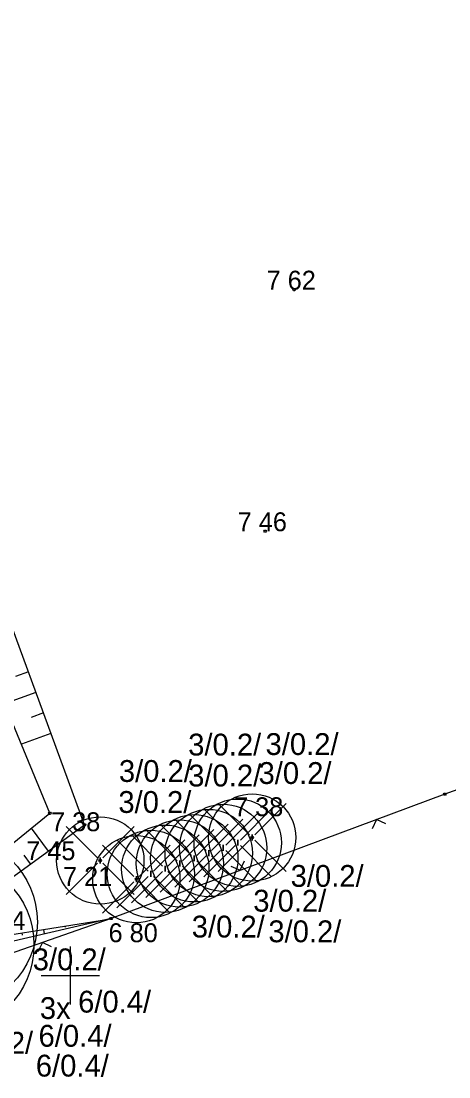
# Model space of a CAD drawing. Extents: x -684336 to -684039, y -993109 to -992688.
# Drawn here: x -684251.69 to -684236.99, y -992903.48 to -992867.21 of the extents above; entities that cross this region are included whole.
import ezdxf

# ---------------------------------------------------------------- set-up
doc = ezdxf.new("R2010")
doc.units = 0
for name, color, linetype in [('51', 7, 'Continuous'), ('53', 7, 'Continuous'), ('57', 7, 'Continuous'), ('60', 7, 'Continuous'), ('70', 7, 'Continuous')]:
    doc.layers.add(name, color=color, linetype=linetype)

msp = doc.modelspace()

# ---------------------------------------------------------------- linework, layer by layer
at = {"layer": '51'}
for points in [[(-684227.21, -992890.21), (-684237.13, -992893.77), (-684248.6, -992898.04), (-684263.09, -992903.1), (-684268.1, -992883.39), (-684271.29, -992870.41), (-684274.7, -992857.04), (-684277.74, -992844.67), (-684280.1, -992835.85), (-684277.64, -992831.2), (-684264.34, -992827.86), (-684252.53, -992824.88)], [(-684248.6, -992898.04), (-684259.12, -992900.48), (-684263.07, -992897.6), (-684268.1, -992883.39), (-684270.5, -992870.3), (-684273.42, -992856.49), (-684276.84, -992844.62), (-684278.77, -992835.66), (-684276.49, -992831.3), (-684269.75, -992830.75), (-684275.57, -992832.23), (-684276.67, -992834.45), (-684274.82, -992844.3), (-684272.25, -992856.25), (-684269.2, -992870.13), (-684265.12, -992882.99), (-684260.21, -992898.51), (-684256.26, -992899.36), (-684254.25, -992898.95), (-684248.751, -992898.075)], [(-684239.151, -992894.789), (-684239.473, -992894.642), (-684239.62, -992894.964)], [(-684244.48, -992896.24), (-684244.159, -992896.387), (-684244.012, -992896.065)], [(-684250.642, -992899.018), (-684250.96, -992898.864), (-684251.114, -992899.183)]]:
    msp.add_lwpolyline(points, dxfattribs=at)
for points in [[(-684268.27, -992833.23), (-684270.44, -992832.08), (-684274.11, -992832.95), (-684275.43, -992835.26), (-684273, -992846.66), (-684269.84, -992859.98), (-684265.88, -992874.62), (-684263.55, -992885.57), (-684260.21, -992896.8), (-684258.4, -992898.8), (-684254.13, -992898.17), (-684249.51, -992894.83), (-684253.29, -992884.54), (-684257.94, -992874.3), (-684263.02, -992858.7), (-684266.06, -992847.54)], [(-684269.72, -992835.11), (-684273.83, -992835.79), (-684272.03, -992846.57), (-684268.48, -992859.73), (-684264.97, -992874.5), (-684262.6, -992885.42), (-684259.03, -992896.58), (-684254.29, -992897.33), (-684250.7, -992894.43), (-684254.64, -992884.91), (-684258.65, -992874.52), (-684264.18, -992858.51), (-684267.32, -992848.18)]]:
    msp.add_lwpolyline(points, close=True, dxfattribs=at)
at = {"layer": '53'}
for points in [[(-684250, -992899), (-684250, -992901)], [(-684251, -992900), (-684249, -992900)]]:
    msp.add_lwpolyline(points, dxfattribs=at)
at = {"layer": '57'}
for points in [[(-684242.288, -992876.402), (-684242.265, -992876.44), (-684242.288, -992876.477), (-684242.333, -992876.477), (-684242.355, -992876.44), (-684242.333, -992876.402)], [(-684243.28, -992884.701), (-684243.258, -992884.739), (-684243.28, -992884.776), (-684243.325, -992884.776), (-684243.348, -992884.739), (-684243.325, -992884.701)], [(-684237.108, -992893.733), (-684237.085, -992893.77), (-684237.108, -992893.807), (-684237.153, -992893.807), (-684237.175, -992893.77), (-684237.153, -992893.733)], [(-684250.677, -992894.393), (-684250.655, -992894.43), (-684250.677, -992894.468), (-684250.722, -992894.468), (-684250.745, -992894.43), (-684250.722, -992894.393)], [(-684249.488, -992894.792), (-684249.465, -992894.83), (-684249.488, -992894.867), (-684249.532, -992894.867), (-684249.555, -992894.83), (-684249.532, -992894.792)], [(-684243.728, -992895.223), (-684243.705, -992895.26), (-684243.728, -992895.298), (-684243.772, -992895.298), (-684243.795, -992895.26), (-684243.772, -992895.223)], [(-684248.948, -992896.013), (-684248.925, -992896.05), (-684248.948, -992896.088), (-684248.992, -992896.088), (-684249.015, -992896.05), (-684248.992, -992896.013)], [(-684247.708, -992896.652), (-684247.685, -992896.69), (-684247.708, -992896.727), (-684247.753, -992896.727), (-684247.775, -992896.69), (-684247.753, -992896.652)], [(-684248.577, -992898.003), (-684248.555, -992898.04), (-684248.577, -992898.078), (-684248.622, -992898.078), (-684248.645, -992898.04), (-684248.622, -992898.003)]]:
    msp.add_lwpolyline(points, close=True, dxfattribs=at)
at = {"layer": '60'}
for points in [[(-684244.339, -992895.347), (-684245.414, -992894.272)], [(-684243.842, -992895.168), (-684244.917, -992894.093)], [(-684244.155, -992895.347), (-684243.08, -992894.272)], [(-684243.658, -992895.168), (-684242.583, -992894.093)], [(-684245.334, -992895.704), (-684246.409, -992894.629)], [(-684244.837, -992895.525), (-684245.912, -992894.45)], [(-684245.15, -992895.704), (-684244.075, -992894.629)], [(-684244.653, -992895.525), (-684243.578, -992894.45)], [(-684249.062, -992895.958), (-684250.137, -992894.883)], [(-684248.878, -992895.958), (-684247.803, -992894.883)], [(-684246.329, -992896.062), (-684247.404, -992894.987)], [(-684245.832, -992895.883), (-684246.907, -992894.808)], [(-684246.145, -992896.062), (-684245.07, -992894.987)], [(-684245.648, -992895.883), (-684244.573, -992894.808)], [(-684247.324, -992896.419), (-684248.399, -992895.344)], [(-684246.827, -992896.241), (-684247.902, -992895.166)], [(-684247.14, -992896.419), (-684246.065, -992895.344)], [(-684246.643, -992896.241), (-684245.568, -992895.166)], [(-684243.842, -992895.352), (-684244.917, -992896.427)], [(-684244.247, -992895.339), (-684244.247, -992895.539), (-684244.247, -992895.339)], [(-684243.75, -992895.16), (-684243.75, -992895.36), (-684243.75, -992895.16)], [(-684243.658, -992895.352), (-684242.583, -992896.427)], [(-684247.822, -992896.598), (-684248.897, -992895.523)], [(-684247.638, -992896.598), (-684246.563, -992895.523)], [(-684244.837, -992895.709), (-684245.912, -992896.784)], [(-684244.339, -992895.531), (-684245.414, -992896.606)], [(-684245.242, -992895.696), (-684245.242, -992895.896), (-684245.242, -992895.696)], [(-684244.745, -992895.517), (-684244.745, -992895.717), (-684244.745, -992895.517)], [(-684244.653, -992895.709), (-684243.578, -992896.784)], [(-684244.155, -992895.531), (-684243.08, -992896.606)], [(-684248.97, -992895.95), (-684248.97, -992896.15), (-684248.97, -992895.95)], [(-684245.832, -992896.067), (-684246.907, -992897.142)], [(-684245.334, -992895.888), (-684246.409, -992896.963)], [(-684246.237, -992896.054), (-684246.237, -992896.254), (-684246.237, -992896.054)], [(-684245.74, -992895.875), (-684245.74, -992896.075), (-684245.74, -992895.875)], [(-684245.648, -992896.067), (-684244.573, -992897.142)], [(-684245.15, -992895.888), (-684244.075, -992896.963)], [(-684249.062, -992896.142), (-684250.137, -992897.217)], [(-684248.878, -992896.142), (-684247.803, -992897.217)], [(-684246.827, -992896.425), (-684247.902, -992897.5)], [(-684246.329, -992896.246), (-684247.404, -992897.321)], [(-684247.232, -992896.411), (-684247.232, -992896.611), (-684247.232, -992896.411)], [(-684246.735, -992896.233), (-684246.735, -992896.433), (-684246.735, -992896.233)], [(-684246.643, -992896.425), (-684245.568, -992897.5)], [(-684246.145, -992896.246), (-684245.07, -992897.321)], [(-684247.822, -992896.782), (-684248.897, -992897.857)], [(-684247.324, -992896.603), (-684248.399, -992897.678)], [(-684247.73, -992896.59), (-684247.73, -992896.79), (-684247.73, -992896.59)], [(-684247.638, -992896.782), (-684246.563, -992897.857)], [(-684247.14, -992896.603), (-684246.065, -992897.678)]]:
    msp.add_lwpolyline(points, dxfattribs=at)
for centre, radius in [((-684244.247, -992895.439), 1.5), ((-684243.75, -992895.26), 1.5), ((-684245.242, -992895.796), 1.5), ((-684244.745, -992895.617), 1.5), ((-684248.97, -992896.05), 1.5), ((-684246.237, -992896.154), 1.5), ((-684245.74, -992895.975), 1.5), ((-684247.232, -992896.511), 1.5), ((-684246.735, -992896.333), 1.5), ((-684254.13, -992898.17), 3), ((-684247.73, -992896.69), 1.5), ((-684254.25, -992898.95), 3)]:
    msp.add_circle(centre, radius, dxfattribs=at)
at = {"layer": '70'}
for points in [[(-684251.441, -992889.573), (-684251.882, -992889.734)], [(-684251.183, -992890.277), (-684252.256, -992890.671)], [(-684250.924, -992890.981), (-684251.342, -992891.134)], [(-684250.665, -992891.685), (-684251.682, -992892.058)], [(-684250.755, -992895.73), (-684251.329, -992894.938)], [(-684251.363, -992896.17), (-684251.583, -992895.866)], [(-684250.182, -992898.303), (-684250.176, -992898.343)], [(-684249.442, -992898.185), (-684249.434, -992898.233)], [(-684251.664, -992898.538), (-684251.651, -992898.62)], [(-684250.923, -992898.421), (-684250.899, -992898.573)]]:
    msp.add_lwpolyline(points, dxfattribs=at)

# ---------------------------------------------------------------- texts
at = {"layer": '57'}
for s, p in [('7 62', (-684243.254, -992876.44)), ('7 46', (-684244.247, -992884.739)), ('7 38', (-684244.372, -992894.529)), ('7 38', (-684250.661, -992895.044)), ('7 45', (-684251.515, -992896.039)), ('7 21', (-684250.251, -992896.925)), ('7 24', (-684253.233, -992898.442)), ('6 80', (-684248.685, -992898.857))]:
    msp.add_text(s, height=0.65, dxfattribs=at).set_placement(p)
at = {"layer": '60'}
for s, p in [('3/0.2/', (-684245.948, -992892.444)), ('3/0.2/', (-684243.289, -992892.426)), ('3/0.2/', (-684248.33, -992893.351)), ('3/0.2/', (-684245.948, -992893.508)), ('3/0.2/', (-684243.531, -992893.421)), ('3/0.2/', (-684248.348, -992894.416)), ('3/0.2/', (-684242.428, -992896.955)), ('3/0.2/', (-684243.711, -992897.807)), ('3/0.2/', (-684245.825, -992898.696)), ('3/0.2/', (-684243.193, -992898.859)), ('3/0.2/', (-684251.291, -992899.822)), ('3x', (-684251.046, -992901.496)), ('6/0.4/', (-684249.731, -992901.275)), ('4/0.2/', (-684253.788, -992902.687)), ('6/0.4/', (-684251.092, -992902.448)), ('6/0.4/', (-684251.185, -992903.473))]:
    msp.add_text(s, height=0.75, dxfattribs=at).set_placement(p)

doc.saveas('drawing.dxf')
